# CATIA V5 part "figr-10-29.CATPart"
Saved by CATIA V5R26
Part number: Part1
Bounding box of the stored display mesh (mm): x -60 to 70, y 0 to 100.393, z 0 to 0
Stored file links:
  D:\_Deepak\CATIA\CATIA V5-6R2016_Deepak\Resources\Part files\Partfiles\c10_catia_v5_6r2016_prt\figr-10-29.CATPart
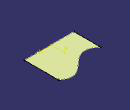
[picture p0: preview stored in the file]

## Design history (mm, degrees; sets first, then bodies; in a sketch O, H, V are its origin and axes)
Set1
  Sweep1: type Segment, GuideCrv (Sketch1; Sketch2), Length1 0, Length2 0
Body1 (main body)
  Sketch1 on xy-plane, origin (0, 0, 0), H (1, 0, 0), V (0, 1, 0)
    line L1 (-60, 0) -> (70, 0)
    point P1 (-60, 0)
    coincidence: P1 H
    horizontal: L1 H
  Sketch2 on xy-plane, origin (0, 0, 0), H (1, 0, 0), V (0, 1, 0)
    spline S1 through (-60, 70) (-20, 60) (40, 100) (70, 90)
